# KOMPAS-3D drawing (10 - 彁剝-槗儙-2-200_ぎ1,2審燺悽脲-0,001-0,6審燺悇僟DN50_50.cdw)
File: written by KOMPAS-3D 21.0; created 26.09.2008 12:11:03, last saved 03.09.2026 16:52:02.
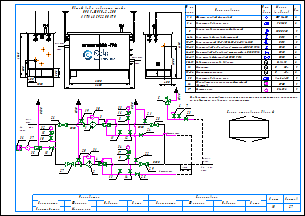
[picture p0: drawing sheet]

Sheets 1-2: A3, landscape

Document properties: Наименование: Макро:21; Автор: RaskoAdmin; Форматы листов документа: 2xA3; Полное имя файла: \\UR38nt01\Departments\КТО\КБ ПУРДГ\Заявки\Прайс-лист на типовые шкафы ГРПШ\ПРДГ_стандарт_20_03_2026\ПРДГ с РДГ(Н, В)\ПРДГ-ШУГО-2-200_до1,2МПа_Рвых-0,001-0,6МПа_РДГ_DN50_50.cdw

Title block, sheet 1: Наименование: Пункт учета газа / ПУГ-Ш-400-Р / ЛГТИ.485922.001ТУ; designation: ЛГТИ.03.4411141; sheet number: 1; Количество листов документа: 2; organisation: ООО "ЭЛЬСТЕР Газэлектроника"; Форматы листов документа: A3; stored path: C:\Рабочие документы\Компас\ПУГ\Схема.cdw; Разработал: Устинов; Проверил: Кошкин; Утвердил: Кошкин
Title block, sheet 2: sheet number: 2; stored path: D:\Рабочие документы\Заявки\ПУРДГ\ПУРДГ-ШУЭО-2-100-Р 4411220.cdw; designation, second copy: ЛГТИ.03.4411141-

Views: Вид 1, Вид 2
Referenced files: wcvoit.frw
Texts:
  Normal
  Вход
  газа
  PDI
  Выход
  Р=     кПа
  DN50
  DN20
  Импульс DN20
  ≥5DN
  HYSWLongFangSong
  Общий вид и габариты шкафа
  ПРДГ-ШУГО-2-200
  Выход газа
  Вход газа
  Р=       МПа
  logo-rasko-ge.png
  № на
  схеме
  Усл.
  обозн.
  Марка
  (модель)
  Кол.
  Фильтр газовый фланцевый
  ФГ 16-50
  Регулятор давления газа
  РДГ-50
  Клапан предохранительный сбросной
  КПС DN20
  Кран шаровой газовый латунный
  DN15
  Кран кнопочный VE-РАСКО-НЗ-1,6-G1/2-М20
  Кран шаровой "под приварку" штуцерный DN20 PN16
  Кран шаровой "под приварку" штуцерный п/п DN20 PN16
  Кран шаровой фланцевый DN50 PN16
  Индикатор перепада давления
  Delta 15
  Манометр
  Манометр-напоромер
  0...     МПа
  0...     кПа
  Обогреватель газогорелочный шкафной
  (Эльтон")
  Счетчик газа
  Venio-A-15
  ОГШН
  BK-G1,6
  Схема открывания дверей
  Предприятие изготовитель может заменять комплектующие на аналогичные,
  не ухудшающие заявленных характеристик.
  Должность
  Конструктор
  Фамилия
  Подпись
  Дата
  Согласовано
  Максимкин
  Лист
  Листов
  POLYLINE_STYLE_0.18_RGB_0_0_0
  POLYLINE_STYLE_0.50_RGB_0_0_0
  POLYLINE_STYLE_0.34_RGB_0_0_0
  PHANTOM_RGB_0_0_0_SC_1_THICK_0.18
  K5LT_THIN_RGB_0_0_0_THICK_0.18
  K5LT32769_RGB_0_0_0_THICK_0.18
  K5LT12_RGB_0_0_0_SC_1_THICK_0.18
  K5LT_DASHED_RGB_0_0_0_SC_1_THICK_0.18
  ACISOTGL_RGB_0_0_0_SC_0.8_THICK_0.25
  CONTINUOUS_RGB_0_127_31_THICK_0.3
  CONTINUOUS_RGB_0_0_255_THICK_0.35
  CONTINUOUS_RGB_255_0_0_THICK_0.35
  POLYLINE_STYLE_0.25_RGB_0_0_0
  CONTINUOUS_RGB_0_0_0_THICK_0.5
  POLYLINE_STYLE_0.35_RGB_0_0_255
  CONTINUOUS_RGB_0_0_0_THICK_0.4
  CONTINUOUS_RGB_0_0_0_THICK_0.35
  Без оформления
Dimensions and other numbers on the sheet: 1; 2; 3; 4; 5; 10; 27; 28; 29; 23; 8; 12; 19; 20; 21; 22; 25; 24; 30; 31; 15; 16; 26; 6; 7; 11; 14; 13; 33; 1000; 400; 1050; 500; 305; 2300; 4130; 1565; 32; 2600; 9; 17; 34; 18; 35; 36; 37; 1, 2; 3, 4; 6-14; 15-17; 18-23; 24-25; 26-29; 30-31; 33-34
